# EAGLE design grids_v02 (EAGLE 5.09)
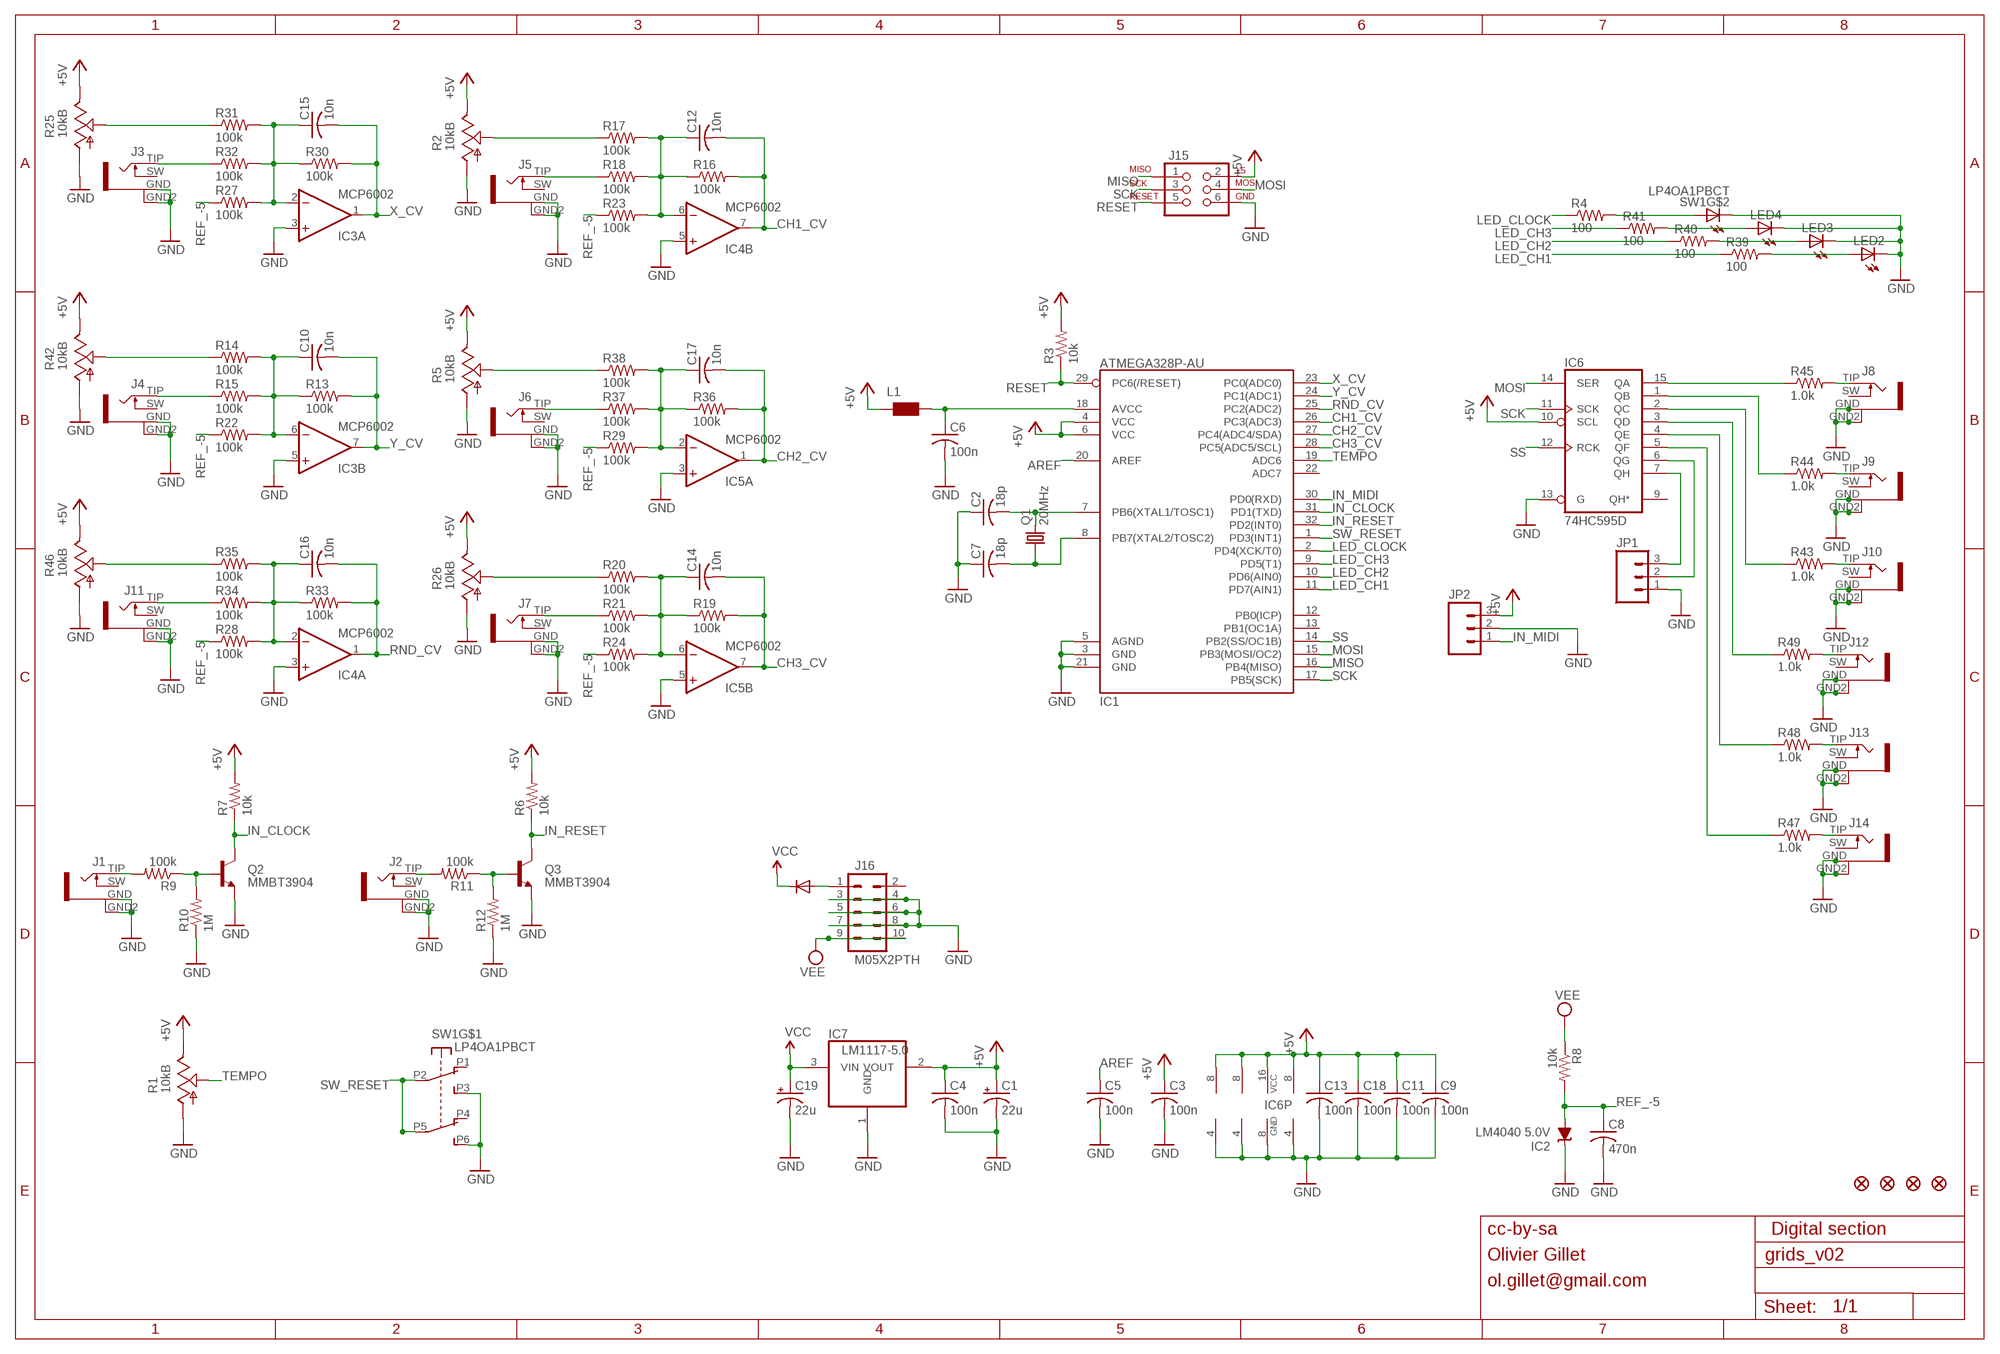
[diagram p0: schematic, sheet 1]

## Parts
C1  22u  CPOL-USC  [PANASONIC_C]
C2  18p  C-USC0603  [C0603]
C3  100n  C-USC0603  [C0603]
C4  100n  C-USC0603  [C0603]
C5  100n  C-USC0603  [C0603]
C6  100n  C-USC0603  [C0603]
C7  18p  C-USC0603  [C0603]
C8  470n  C-USC0603  [C0603]
C9  100n  C-USC0603  [C0603]
C10  10n  C-USC0603  [C0603]
C11  100n  C-USC0603  [C0603]
C12  10n  C-USC0603  [C0603]
C13  100n  C-USC0603  [C0603]
C14  10n  C-USC0603  [C0603]
C15  10n  C-USC0603  [C0603]
C16  10n  C-USC0603  [C0603]
C17  10n  C-USC0603  [C0603]
C18  100n  C-USC0603  [C0603]
C19  22u  CPOL-USC  [PANASONIC_C]
D1  1N5819HW  DIODE-SOD123  [SOD123]
F1  FIDUCIAL1X2  [FIDUCIAL-1X2]
F2  FIDUCIAL1X2  [FIDUCIAL-1X2]
F3  FIDUCIAL1X2  [FIDUCIAL-1X2]
F4  FIDUCIAL1X2  [FIDUCIAL-1X2]
IC1  ATMEGA328P-AU  ATMEGA168  [TQFP32-08]
IC2  LM4040 5.0V  LM4041C12DBZ  [DBZ_R-PDSO-G3]
IC3  MCP6002  TL072D  [SO08]
IC4  MCP6002  TL072D  [SO08]
IC5  MCP6002  TL072D  [SO08]
IC6  74HC595D  [SO16]
IC7  LM1117-5.0  REG1117  [SOT223]
J1  PJ301WQP  [WQP_PJ_301BM]
J2  PJ301WQP  [WQP_PJ_301BM]
J3  PJ301WQP  [WQP_PJ_301BM]
J4  PJ301WQP  [WQP_PJ_301BM]
J5  PJ301WQP  [WQP_PJ_301BM]
J6  PJ301WQP  [WQP_PJ_301BM]
J7  PJ301WQP  [WQP_PJ_301BM]
J8  PJ301WQP  [WQP_PJ_301BM]
J9  PJ301WQP  [WQP_PJ_301BM]
J10  PJ301WQP  [WQP_PJ_301BM]
J11  PJ301WQP  [WQP_PJ_301BM]
J12  PJ301WQP  [WQP_PJ_301BM]
J13  PJ301WQP  [WQP_PJ_301BM]
J14  PJ301WQP  [WQP_PJ_301BM]
J15  AVR_SPI_PRG_6PTH  [2X3]
J16  M05X2PTH  [AVR_ICSP]
JP1  M03PTH  [1X03]
JP2  M03PTH  [1X03]
L1  WE-CBF_0603  [0603]
LED2  LED3MM  [LED3MM]
LED3  LED3MM  [LED3MM]
LED4  LED3MM  [LED3MM]
Q1  20MHz  CRYSTALHC49UP  [HC49UP]
Q2  MMBT3904  MMBT3904LT1-NPN-SOT23-BEC  [SOT23-BEC]
Q3  MMBT3904  MMBT3904LT1-NPN-SOT23-BEC  [SOT23-BEC]
R1  10kB  POT_USVERTICAL_PS  [ALPS_POT_VERTICAL_PS]
R2  10kB  POT_USVERTICAL_PS  [ALPS_POT_VERTICAL_PS]
R3  10k  R-US_R0603  [R0603]
R4  100  R-US_R0603  [R0603]
R5  10kB  POT_USVERTICAL_PS  [ALPS_POT_VERTICAL_PS]
R6  10k  R-US_R0603  [R0603]
R7  10k  R-US_R0603  [R0603]
R8  10k  R-US_R0603  [R0603]
R9  100k  R-US_R0603  [R0603]
R10  1M  R-US_R0603  [R0603]
R11  100k  R-US_R0603  [R0603]
R12  1M  R-US_R0603  [R0603]
R13  100k  R-US_R0603  [R0603]
R14  100k  R-US_R0603  [R0603]
R15  100k  R-US_R0603  [R0603]
R16  100k  R-US_R0603  [R0603]
R17  100k  R-US_R0603  [R0603]
R18  100k  R-US_R0603  [R0603]
R19  100k  R-US_R0603  [R0603]
R20  100k  R-US_R0603  [R0603]
R21  100k  R-US_R0603  [R0603]
R22  100k  R-US_R0603  [R0603]
R23  100k  R-US_R0603  [R0603]
R24  100k  R-US_R0603  [R0603]
R25  10kB  POT_USVERTICAL_PS  [ALPS_POT_VERTICAL_PS]
R26  10kB  POT_USVERTICAL_PS  [ALPS_POT_VERTICAL_PS]
R27  100k  R-US_R0603  [R0603]
R28  100k  R-US_R0603  [R0603]
R29  100k  R-US_R0603  [R0603]
R30  100k  R-US_R0603  [R0603]
R31  100k  R-US_R0603  [R0603]
R32  100k  R-US_R0603  [R0603]
R33  100k  R-US_R0603  [R0603]
R34  100k  R-US_R0603  [R0603]
R35  100k  R-US_R0603  [R0603]
R36  100k  R-US_R0603  [R0603]
R37  100k  R-US_R0603  [R0603]
R38  100k  R-US_R0603  [R0603]
R39  100  R-US_R0603  [R0603]
R40  100  R-US_R0603  [R0603]
R41  100  R-US_R0603  [R0603]
R42  10kB  POT_USVERTICAL_PS4  [ALPS_POT_VERTICAL_PS4]
R43  1.0k  R-US_R0603  [R0603]
R44  1.0k  R-US_R0603  [R0603]
R45  1.0k  R-US_R0603  [R0603]
R46  10kB  POT_USVERTICAL_PS  [ALPS_POT_VERTICAL_PS]
R47  1.0k  R-US_R0603  [R0603]
R48  1.0k  R-US_R0603  [R0603]
R49  1.0k  R-US_R0603  [R0603]
SW1  LP4OA1PBCT  [LP4OA1PBCT]

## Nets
+5V: C1.+ C3.1 C4.1 C9.1 C11.1 C13.1 C18.1 IC1.4(VCC) IC1.6(VCC) IC3.8(P:V+) IC4.8(P:V+) IC5.8(P:V+) IC6.10(SCL) IC6.16(VCC) IC7.2(VOUT) J15.2 JP2.3 L1.1 R1.P$1(E) R2.P$1(E) R3.2 R5.P$1(E) R6.2 R7.2 R25.P$1(E) R26.P$1(E) R42.P$1(E) R46.P$1(E)
AREF: C5.1 IC1.20(AREF)
CH1_CV: C12.2 IC1.26(PC3(ADC3)) IC4.7(B:OUT) R16.2
CH2_CV: C17.2 IC1.27(PC4(ADC4/SDA)) IC5.1(A:OUT) R36.2
CH3_CV: C14.2 IC1.28(PC5(ADC5/SCL)) IC5.7(B:OUT) R19.2
CLOCK_OUT: IC6.6(QG) JP1.2
GATE1_IN: J1.TIP R9.2
GATE1_LED: R4.2 SW1.L1
GATE2_IN: J2.TIP R11.2
GATE2_LED: LED4.A R41.2
GATE3_LED: LED3.A R40.2
GATE4_LED: LED2.A R39.2
GND: C1.- C2.1 C3.2 C4.2 C5.2 C6.2 C7.1 C8.2 C9.2 C11.2 C13.2 C18.2 C19.- IC1.3(GND) IC1.5(AGND) IC1.21(GND) IC2.1(C) IC3.3(A:+IN) IC3.4(P:V-) IC3.5(B:+IN) IC4.3(A:+IN) IC4.4(P:V-) IC4.5(B:+IN) IC5.3(A:+IN) IC5.4(P:V-) IC5.5(B:+IN) IC6.8(GND) IC6.13(G) IC7.1(GND) J1.GND J1.GND2 J2.GND J2.GND2 J3.GND J3.GND2 J4.GND J4.GND2 J5.GND J5.GND2 J6.GND J6.GND2 J7.GND J7.GND2 J8.GND J8.GND2 J9.GND J9.GND2 J10.GND J10.GND2 J11.GND J11.GND2 J12.GND J12.GND2 J13.GND J13.GND2 J14.GND J14.GND2 J15.6 J16.3 J16.4 J16.5 J16.6 J16.7 J16.8 JP1.1 JP2.2 LED2.K(C) LED3.K(C) LED4.K(C) Q2.E Q3.E R1.P$3(A) R2.P$3(A) R5.P$3(A) R10.1 R12.1 R25.P$3(A) R26.P$3(A) R42.P$3(A) R46.P$3(A) SW1.L2 SW1.P3(A3) SW1.P6(B3)
IN_CLOCK: IC1.31(PD1(TXD)) Q2.C R7.1
IN_MIDI: IC1.30(PD0(RXD)) JP2.1
IN_RESET: IC1.32(PD2(INT0)) Q3.C R6.1
LED_CH1: IC1.11(PD7(AIN1)) R39.1
LED_CH2: IC1.10(PD6(AIN0)) R40.1
LED_CH3: IC1.9(PD5(T1)) R41.1
LED_CLOCK: IC1.2(PD4(XCK/T0)) R4.1
MISO: IC1.16(PB4(MISO)) J15.1
MOSI: IC1.15(PB3(MOSI/OC2)) IC6.14(SER) J15.4
N$1: Q2.B R9.1 R10.2
N$2: Q3.B R11.1 R12.2
N$3: D1.A J16.1
N$4: J14.TIP R47.2
N$5: J13.TIP R48.2
N$6: J12.TIP R49.2
N$9: R25.P$2(S) R31.1
N$10: J3.TIP R32.1
N$12: C10.1 IC3.6(B:-IN) R13.1 R14.2 R15.2 R22.2
N$13: R14.1 R42.P$2(S)
N$14: J4.TIP R15.1
N$15: C16.1 IC4.2(A:-IN) R28.2 R33.1 R34.2 R35.2
N$16: R35.1 R46.P$2(S)
N$17: J11.TIP R34.1
N$18: C12.1 IC4.6(B:-IN) R16.1 R17.2 R18.2 R23.2
N$19: R2.P$2(S) R17.1
N$20: J5.TIP R18.1
N$21: C17.1 IC5.2(A:-IN) R29.2 R36.1 R37.2 R38.2
N$22: R5.P$2(S) R38.1
N$23: J6.TIP R37.1
N$24: C14.1 IC5.6(B:-IN) R19.1 R20.2 R21.2 R24.2
N$25: R20.1 R26.P$2(S)
N$26: J7.TIP R21.1
N$27: IC6.15(QA) R45.1
N$28: IC6.1(QB) R44.1
N$29: C15.1 IC3.2(A:-IN) R27.2 R30.1 R31.2 R32.2
N$30: IC6.2(QC) R43.1
N$31: IC6.3(QD) R49.1
N$32: IC6.4(QE) R48.1
N$33: IC6.5(QF) R47.1
N$34: J8.TIP R45.2
N$35: J9.TIP R44.2
N$36: J10.TIP R43.2
N$39: C6.1 IC1.18(AVCC) L1.2
N$82: C7.2 IC1.8(PB7(XTAL2/TOSC2)) Q1.1
N$83: C2.2 IC1.7(PB6(XTAL1/TOSC1)) Q1.2
RANDOM_GATE: IC6.7(QH) JP1.3
REF_-5: C8.1 IC2.2(A) R8.2 R22.1 R23.1 R24.1 R27.1 R28.1 R29.1
RESET: IC1.29(PC6(/RESET)) J15.5 R3.1
RND_CV: C16.2 IC1.25(PC2(ADC2)) IC4.1(A:OUT) R33.2
SCK: IC1.17(PB5(SCK)) IC6.11(SCK) J15.3
SS: IC1.14(PB2(SS/OC1B)) IC6.12(RCK)
SW_RESET: IC1.1(PD3(INT1)) SW1.P2(A2) SW1.P5(B2)
TEMPO: IC1.19(ADC6) R1.P$2(S)
VCC: C19.+ D1.C IC7.3(VIN)
VEE: J16.9 J16.10 R8.1
X_CV: C15.2 IC1.23(PC0(ADC0)) IC3.1(A:OUT) R30.2
Y_CV: C10.2 IC1.24(PC1(ADC1)) IC3.7(B:OUT) R13.2
Unconnected: IC1.12(PB0(ICP)) IC1.13(PB1(OC1A)) IC1.22(ADC7) IC6.9(QH*) J1.SW J2.SW J3.SW J4.SW J5.SW J6.SW J7.SW J8.SW J9.SW J10.SW J11.SW J12.SW J13.SW J14.SW J16.2 SW1.P1(A1) SW1.P4(B1)

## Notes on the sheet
- cc-by-sa | Digital section
- Olivier Gillet
- ol.gillet@gmail.com

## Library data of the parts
C1 C19 = rcl:CPOL-US: POLARIZED CAPACITOR, American symbol
C2-C18 = rcl:C-US: CAPACITOR, American symbol
D1 = diode:DIODE-: DIODE
F1-F4 = SparkFun:FIDUCIAL: Fiducial Alignment Points
IC1 = SparkFun:ATMEGA168
IC2 = texas:LM4041: PRECISION MICROPOWER SHUNT VOLTAGE REFERENCE
IC3-IC5 = og-linear:TL072: OP AMP
IC6 = 74xx-eu:74*595: 8-bit SHIFT REGISTER, output latch
IC7 = og-vreg:REG1117: 800mA and 1A Low Dropout (LDO) Positive Regulator 1.8V, 2.5V, 2.85V, 3.3V, 5V, and Adj
J1-J14 = og-pj301:PJ301
J15 = SparkFun:AVR_SPI_PRG_6: AVR ISP 6 Pin This is the reduced ISP connector for AVR programming. Common on Arduino. This footprint will take up less PCB space and can be used with a 10-pin to 6-pin adapter such as SKU: BOB-08508
J16 = og-header:M05X2: Header 5x2 Standard 10-pin dual row 0.1" header. Commonly used with AVR-ISP. Use with Spark Fun Electronics SKU: PRT-00778
JP1 JP2 = SparkFun:M03: Header 3 Standard 3-pin 0.1" header. Use with straight break away headers (SKU : PRT-00116), right angle break away headers (PRT-00553), swiss pins (PRT-00743), machine pins (PRT-00117), and female headers (PRT-00115). Molex polarized connector foot print use with SKU : PRT-08232 with associated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
L1 = wuerth-elektronik:WE-CBF: SMD EMI Suppression Ferrite Beads
LED2-LED4 = led:LED: LED
Q1 = crystal:CRYSTAL: CRYSTAL
Q2 Q3 = transistor:*-NPN-: NPN Transistror BF959 corrected 2008.03.06
R1 R2 R5 R25 R26 R42 R46 = pot-alps:POT_US
R3 R4 R6 R7 R9-R24 R27-R41 R43-R45 R47-R49 = rcl:R-US_: RESISTOR, American symbol
R8 = resistor:R-US_: RESISTOR, American symbol
SW1 = og-switch:LP4OA1PBCT

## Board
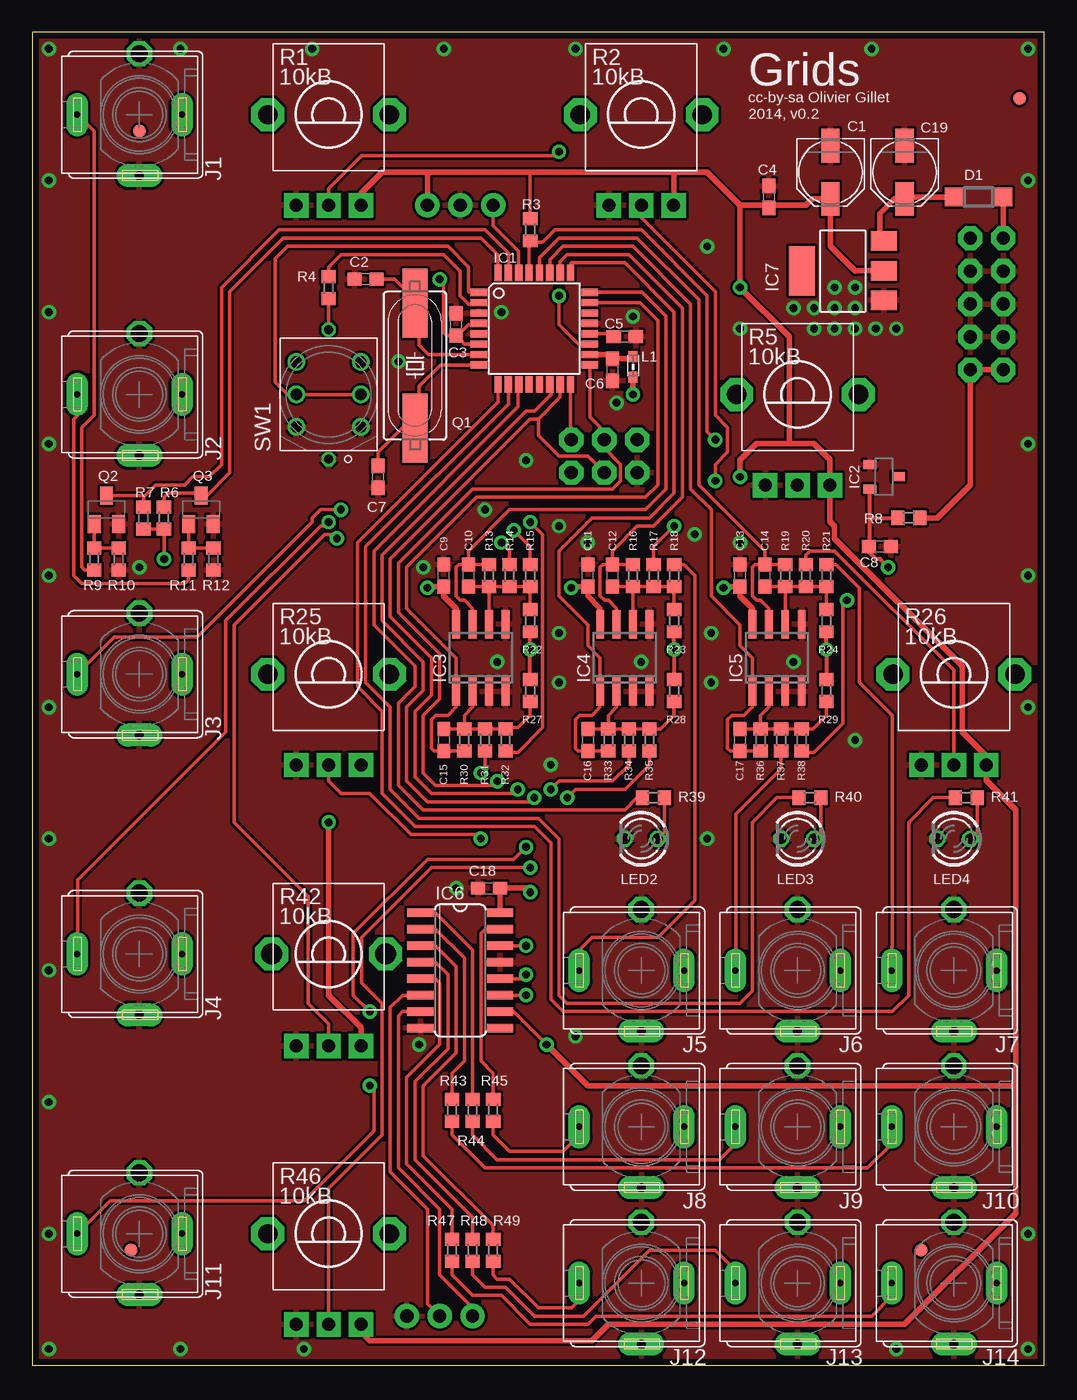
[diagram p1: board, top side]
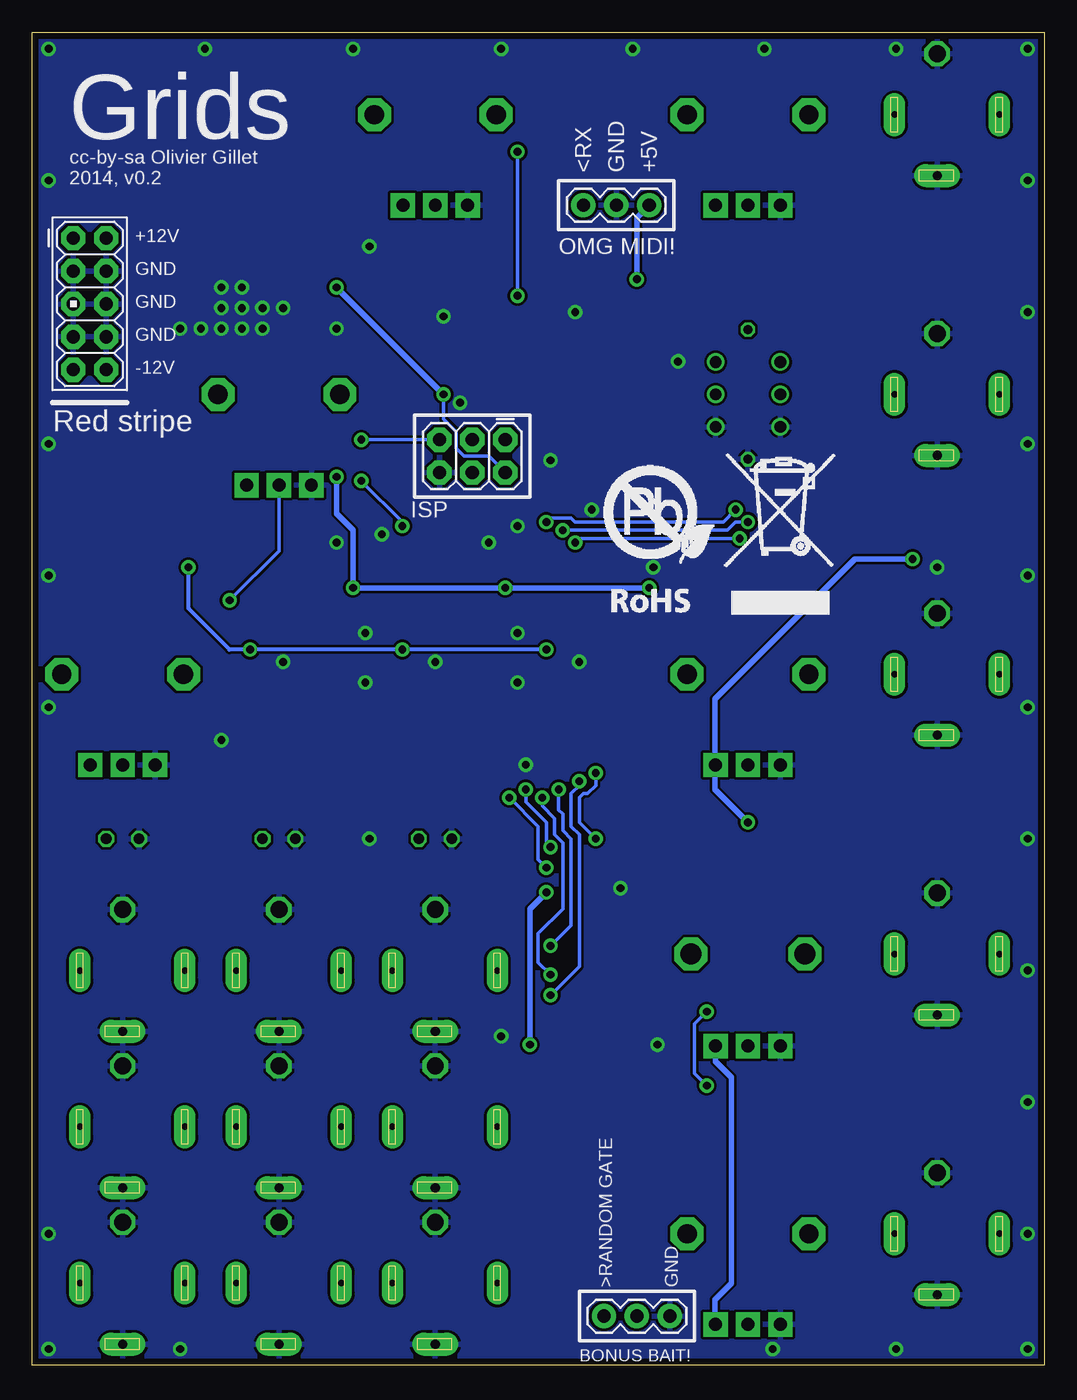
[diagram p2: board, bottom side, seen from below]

Size 78.08 x 102.87 mm. Coordinates in mm from the lower left corner, seen from the top.
Outline: 0,0 78.08,0 78.08,102.87 0,102.87 0,0
Copper layers (1*16): Top 0.035mm / dielectric 1.5mm / Bottom 0.035mm
Design rules "PCBCart-Standard *": minimum track width 8mil, minimum drill 0.4mm, track to track 8mil, track to pad 8mil, pad to pad 8mil, via to via 8mil, smd to smd 8mil, copper to edge 20mil, drill to drill 8mil, minimum pad ring 8mil, minimum via ring 10mil, stop-mask expansion 3mil, vias tented up to drill 25mil, thermal gap 8mil

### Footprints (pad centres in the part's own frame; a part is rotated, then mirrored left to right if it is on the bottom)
PANASONIC_C = smd 2.6 x 1.4: + 2.05,0; - -2.05,0
C0603 = smd 1.1 x 1: 1 -0.85,0; 2 0.85,0
SOD123 = smd 1.4 x 1.4: A 1.9,0; C -1.9,0
FIDUCIAL-1X2 = smd 1 x 1: 1 0,0
TQFP32-08 = smd 1.27 x 0.559: 1 -4.293,2.8; 2 -4.293,2; 3 -4.293,1.2; 4 -4.293,0.4; 5 -4.293,-0.4; 6 -4.293,-1.2; 7 -4.293,-2; 8 -4.293,-2.8; 17 4.293,-2.8; 18 4.293,-2; 19 4.293,-1.2; 20 4.293,-0.4; 21 4.293,0.4; 22 4.293,1.2; 23 4.293,2; 24 4.293,2.8 | smd 0.559 x 1.27: 9 -2.8,-4.293; 10 -2,-4.293; 11 -1.2,-4.293; 12 -0.4,-4.293; 13 0.4,-4.293; 14 1.2,-4.293; 15 2,-4.293; 16 2.8,-4.293; 25 2.8,4.293; 26 2,4.293; 27 1.2,4.293; 28 0.4,4.293; 29 -0.4,4.293; 30 -1.2,4.293; 31 -2,4.293; 32 -2.8,4.293
DBZ_R-PDSO-G3 = smd 0.7 x 1: 1 -0.95,-1.1; 2 0.95,-1.1; 3 0,1.1
SO08 = smd 0.6 x 2.2: 1 -1.905,-2.6; 2 -0.635,-2.6; 3 0.635,-2.6; 4 1.905,-2.6; 5 1.905,2.6; 6 0.635,2.6; 7 -0.635,2.6; 8 -1.905,2.6
SO16 = smd 0.66 x 2.032: 1 -4.445,-3.073; 2 -3.175,-3.073; 3 -1.905,-3.073; 4 -0.635,-3.073; 5 0.635,-3.073; 6 1.905,-3.073; 7 3.175,-3.073; 8 4.445,-3.073; 9 4.445,3.073; 10 3.175,3.073; 11 1.905,3.073; 12 0.635,3.073; 13 -0.635,3.073; 14 -1.905,3.073; 15 -3.175,3.073; 16 -4.445,3.073
SOT223 = smd 1.499 x 2.007: 1 -2.261,-3.15; 2 0.025,-3.15; 3 2.311,-3.15 | smd 3.81 x 2.007: 4 0,3.15
WQP_PJ_301BM = drill 0.7 pad 1.778 long: GND -4.7,0 | drill 1.3 octagon: GND2 4.7,0 | drill 0.5 pad 1.676 long: SW 0,-3.3; TIP 0,4.8
2X3 = drill 1.016 pad 1.88 octagon: 1 0,0; 2 0,2.54; 3 2.54,0; 4 2.54,2.54; 5 5.08,0; 6 5.08,2.54
AVR_ICSP = drill 1.016 pad 1.88 octagon: 1 -1.27,5.08; 2 1.27,5.08; 3 -1.27,2.54; 4 1.27,2.54; 5 -1.27,0; 6 1.27,0; 7 -1.27,-2.54; 8 1.27,-2.54; 9 -1.27,-5.08; 10 1.27,-5.08
1X03 = drill 1.016 pad 1.88 round: 1 0,0; 2 2.54,0; 3 5.08,0
0603 = smd 0.85 x 0.7: 1 -0.9,0; 2 0.7,0
LED3MM = drill 0.813 octagon: A -1.27,0; K 1.27,0
HC49UP = smd 5.334 x 1.93: 1 -4.826,0; 2 4.826,0
SOT23-BEC = smd 1 x 1.4: B -0.95,-1.1; C 0,1.1; E 0.95,-1.1
ALPS_POT_VERTICAL_PS = drill 1 pad 1.88 square: P$1 -2.5,7; P$2 0,7; P$3 2.5,7 | drill 1.5 pad 2.54 octagon: P$4 -4.7,0; P$5 4.7,0
R0603 = smd 1 x 1.1: 1 -0.85,0; 2 0.85,0
ALPS_POT_VERTICAL_PS4 = drill 1 pad 1.88 square: P$1 -2.5,7.1; P$2 0,7.1; P$3 2.5,7.1 | drill 1.6 pad 2.54 octagon: P$4 -4.4,0; P$5 4.4,0
LP4OA1PBCT = drill 0.7 octagon: L1 5,0; L2 -5,0 | drill 0.9 round: P1 2.5,2.5; P2 0,2.5; P3 -2.5,2.5; P4 2.5,-2.5; P5 0,-2.5; P6 -2.5,-2.5

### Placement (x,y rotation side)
C1  61.59,92.08 270 top
C2  25.72,83.82 0 top
C3  32.7,80.33 90 top
C4  56.83,90.17 90 top
C5  45.72,79.38 0 top
C6  44.77,76.83 270 top
C7  26.67,68.58 90 top
C8  65.41,63.18 0 top
C9  31.75,60.96 90 top
C10  33.66,60.96 90 top
C11  42.86,60.96 90 top
C12  44.77,60.96 90 top
C13  54.61,60.96 90 top
C14  56.52,60.96 90 top
C15  31.75,48.26 270 top
C16  42.86,48.26 270 top
C17  54.61,48.26 270 top
C18  35.24,36.83 180 top
C19  67.31,92.08 270 top
D1  73.03,90.17 0 top
F1  76.2,97.79 90 top
F2  8.26,95.25 90 top
F3  7.62,8.89 90 top
F4  68.58,8.89 90 top
IC1  38.73,80.01 0 top
IC2  65.72,68.58 270 top
IC3  34.61,54.61 0 top
IC4  45.72,54.61 0 top
IC5  57.47,54.61 0 top
IC6  33.02,30.48 270 top
IC7  62.55,84.45 90 top
J1  8.26,96.52 90 top
J2  8.26,74.93 90 top
J3  8.26,53.34 90 top
J4  8.26,31.75 90 top
J5  46.99,30.48 90 top
J6  59.05,30.48 90 top
J7  71.12,30.48 90 top
J8  46.99,18.41 90 top
J9  59.05,18.41 90 top
J10  71.12,18.41 90 top
J11  8.26,10.16 90 top
J12  46.99,6.35 90 top
J13  59.05,6.35 90 top
J14  71.12,6.35 90 top
J15  41.59,71.44 180 bottom
J16  73.66,81.92 0 bottom
JP1  28.89,3.81 180 bottom
JP2  35.56,89.53 0 bottom
L1  46.35,77.15 90 top
LED2  46.99,40.64 180 top
LED3  59.05,40.64 180 top
LED4  71.12,40.64 180 top
Q1  29.53,77.15 90 top
Q2  5.71,66.04 0 top
Q3  13.02,66.04 0 top
R1  22.86,96.52 180 top
R2  46.99,96.52 180 top
R3  38.42,87.63 90 top
R4  22.86,83.19 270 top
R5  59.05,74.93 180 top
R6  10.16,65.41 270 top
R7  8.57,65.41 270 top
R8  67.63,65.41 180 top
R9  4.76,62.23 270 top
R10  6.67,62.23 90 top
R11  12.06,62.23 270 top
R12  13.97,62.23 90 top
R13  35.24,60.96 90 top
R14  36.83,60.96 270 top
R15  38.42,60.96 270 top
R16  46.35,60.96 90 top
R17  47.94,60.96 270 top
R18  49.53,60.96 270 top
R19  58.1,60.96 90 top
R20  59.69,60.96 270 top
R21  61.28,60.96 270 top
R22  38.42,57.47 90 top
R23  49.53,57.47 90 top
R24  61.28,57.47 90 top
R25  22.86,53.34 180 top
R26  71.12,53.34 180 top
R27  38.42,52.07 270 top
R28  49.53,52.07 270 top
R29  61.28,52.07 270 top
R30  33.34,48.26 270 top
R31  34.92,48.26 90 top
R32  36.51,48.26 90 top
R33  44.45,48.26 270 top
R34  46.04,48.26 90 top
R35  47.62,48.26 90 top
R36  56.2,48.26 270 top
R37  57.78,48.26 90 top
R38  59.37,48.26 90 top
R39  47.94,43.81 0 top
R40  60.01,43.81 0 top
R41  72.07,43.81 0 top
R42  22.86,31.75 180 top
R43  32.38,19.68 270 top
R44  33.97,19.68 270 top
R45  35.56,19.68 270 top
R46  22.86,10.16 180 top
R47  32.38,8.89 270 top
R48  33.97,8.89 270 top
R49  35.56,8.89 270 top
SW1  22.86,74.93 90 top
U$1  [EURORACK_TEMPLATE]  not placed on the board
U$2  [ROHS_BIG]  35.24,57.15 0 bottom

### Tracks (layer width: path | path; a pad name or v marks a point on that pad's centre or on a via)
+5V  (via drill 0.6)
  Top 0.254: v39.69,24.77 37.15,27.3 IC6.10 | 38.42,92.08 R3.2 | 34.51,78.74 IC1.6 33.37,78.81 33.07,79.11 | v10.16,62.23 R6.2 R7.2 | v31.43,83.82 31.75,83.5 31.75,79.69 31.96,79.48 C3.1 33.07,79.11 | IC1.4 34.36,80.33 33.66,80.33 33.07,79.74 33.07,79.11
  Top 0.406: 30.48,92.08 26.99,92.08 25.36,90.45 R1.P$1 | 30.48,92.08 38.42,92.08 49.53,92.08 | v39.69,24.77 42.86,21.59 75.88,21.59 | IC3.8 32.66,57.25 32.7,57.3 32.7,58.42 31.75,59.37 C9.1 30.58,60.11 v30.48,60.01 | IC4.8 43.77,57.25 43.81,57.3 43.81,58.42 42.86,59.37 C11.1 41.7,60.11 v41.59,60.01 | v46.35,74.93 L1.1 | IC5.8 55.56,58.42 54.61,59.37 C13.1 | C13.1 54.51,60.01 | v38.42,36.51 38.1,36.83 C18.1 IC6.16 | v22.86,41.91 22.86,28.57 25.36,26.07 R42.P$1 | 75.88,21.59 75.88,42.86 73.62,45.12 R26.P$1 73.66,46.38 73.66,46.99 71.75,48.9 71.75,53.98 61.91,63.82 61.91,64.77 61.55,65.13 R5.P$1 61.55,69.89 60.33,71.12 58.42,71.12 | R46.P$1 25.36,2.58 26.04,1.91 43.18,1.91 44.45,3.17 67.31,3.17 75.88,11.75 75.88,21.59 | v53.34,60.01 53.44,60.11 C13.1 | v54.61,68.58 54.61,69.85 55.88,71.12 58.42,71.12 | 30.48,92.08 JP2.3 | R2.P$1 49.53,89.56 49.53,92.08 | 58.42,71.12 58.42,79.38 v54.61,83.19 54.61,89.53 | IC7.2 63.5,84.48 63.5,84.45 61.59,86.36 C1.+ 60.18,90.03 59.69,89.53 57.05,89.53 C4.1 56.62,89.53 54.61,89.53 | 49.53,92.08 52.07,92.08 54.61,89.53
  Bottom 0.254: J15.2 42.86,70.17 44.77,70.17 45.4,70.8 45.4,72.07 46.35,73.03 v46.35,74.93
  Bottom 0.406: v39.69,24.77 39.69,35.24 v38.42,36.51 | v30.48,60.01 v41.59,60.01 v53.34,60.01 53.34,64.45 54.61,65.72 v54.61,68.58 | v54.61,83.19 v46.35,74.93 | JP2.3 31.43,88.58 v31.43,83.82 | v22.86,41.91 25.4,44.45 25.4,46.3 R25.P$1 25.36,46.64 25.4,46.68 25.4,51.44 14.61,62.23 v10.16,62.23 | R46.P$1 25.4,3.2 25.4,5.08 24.13,6.35 24.13,22.23 25.36,23.45 R42.P$1
AREF
  Top 0.254: C5.1 44.63,79.61 IC1.20
CH1_CV
  Top 0.254: IC4.7 45.09,58.42 44.45,59.05 44.13,59.05 43.81,59.37 43.81,61.59 44.03,61.81 C12.2 | C12.2 R16.2 | C12.2 44.77,62.87 46.67,64.77 47.94,64.77 50.16,66.99 50.16,81.6 46.04,85.72 41.27,85.72 40.73,85.19 IC1.26
CH2_CV
  Top 0.254: IC1.27 39.94,85.34 40.96,86.36 46.35,86.36 50.8,81.92 50.8,67.63 52.39,66.04 52.39,59.37 54.61,57.15 54.61,55.56 55.56,54.61 IC5.1 55.56,50.8 54.93,50.16 53.98,50.16 53.66,49.85 53.66,47.62 53.87,47.41 C17.2 R36.2
CH3_CV
  Top 0.254: C14.2 56.52,62.87 51.44,67.94 51.44,82.23 46.67,87 40.64,87 39.13,85.49 IC1.28 | IC5.7 56.83,58.42 56.2,59.05 55.88,59.05 55.56,59.37 55.56,61.59 55.78,61.81 C14.2 | C14.2 R19.2
CLOCK_OUT
  Top 0.254: IC6.6 28.57,28.57 27.62,27.62 27.62,14.92 30.48,12.06 30.48,4.76 JP1.2
GATE1_IN
  Top 0.254: R9.2 4.03,61.38 3.81,61.59 3.81,72.39 4.76,73.34 4.76,95.25 3.49,96.52 J1.TIP
GATE1_LED
  Top 0.254: SW1.L1 R4.2
GATE2_IN
  Top 0.254: J2.TIP 3.49,74.89 3.49,73.34 3.17,73.03 3.17,60.96 3.81,60.33 11.75,60.33 12.06,60.64 R11.2
GATE2_LED
  Top 0.254: LED4.A 72.92,41.17 R41.2
GATE3_LED
  Top 0.254: LED3.A 60.86,41.17 R40.2
GATE4_LED
  Top 0.254: LED2.A 48.79,41.17 R39.2
GND  (via drill 0.6)
  other vias: 8.26,61.59 46.35,80.96 46.99,54.29 58.74,54.29 42.86,63.5 54.61,63.5 35.88,54.29 30.16,61.59 45.09,74.3 36.2,81.28 40.01,46.35 40.64,52.7 32.7,36.83 29.84,24.77 28.26,77.47 52.07,86.36 54.61,80.01 38.1,69.85 52.39,52.7 40.64,56.52 52.39,56.52 41.91,25.4 34.92,66.04 40.64,64.77 51.12,64.14 1.27,20.32 11.43,1.27 1.27,30.48 1.27,81.28 1.27,91.44 20.95,1.27 1.27,101.6 1.27,1.27 63.5,48.26 76.83,101.6 76.83,91.44 76.83,71.12 76.83,60.96 76.83,50.8 76.83,1.27 66.67,1.27 76.83,10.16 52.07,40.64 1.27,60.96 1.27,50.8 1.27,71.12 1.27,40.64 1.27,10.16 11.43,101.6 21.59,101.6 31.75,101.6 41.91,101.6 53.34,101.6 64.77,101.6 63.5,83.19 63.5,81.6 61.91,83.19 61.91,81.6 63.5,80.01 65.09,80.01 61.91,80.01 66.67,80.01 60.33,80.01 60.33,81.6 58.74,81.6
  pour Bottom: 0,102.87 0,0 78.11,0 78.11,102.87
  pour Top: 0,102.87 0,0 78.11,0 78.11,102.87
IN_CLOCK
  Top 0.254: 8.57,66.99 9.53,67.94 11.75,67.94 12.38,68.58 13.65,68.58 14.61,69.53 14.61,83.19 19.05,87.63 34.92,87.63 36.73,85.82 IC1.31 | 8.57,66.99 R7.1 | 8.57,66.99 8.43,67.14 Q2.C
IN_MIDI
  Top 0.254: JP2.1 35.56,87.95 37.53,85.97 IC1.30
IN_RESET
  Top 0.254: IC1.32 35.94,85.67 34.61,87 19.37,87 15.24,82.87 15.24,68.9 13.48,67.14 Q3.C 12.85,67.31 10.48,67.31 10.16,66.99 R6.1
LED_CH1
  Top 0.254: IC1.11 37.47,75.65 37.47,73.98 26.35,62.87 26.35,57.15 29.53,53.98 29.53,52.39 28.26,51.12 28.26,44.77 30.16,42.86 45.72,42.86 46.67,43.81 R39.1
LED_CH2
  Top 0.254: 36.83,75.62 IC1.10 36.73,74.2 25.72,63.18 25.72,52.7 27.62,50.8 27.62,44.45 29.84,42.23 39.05,42.23 40.64,40.64 40.64,28.57 41.27,27.94 54.61,27.94 55.56,28.89 55.56,41.91 57.47,43.81 R40.1
LED_CH3
  Top 0.254: 35.88,75.66 IC1.9 35.94,74.35 25.08,63.5 25.08,52.39 26.99,50.48 26.99,44.13 29.53,41.59 38.73,41.59 40.01,40.32 40.01,28.26 40.96,27.3 66.36,27.3 67.63,28.57 67.63,41.91 69.53,43.81 R41.1
LED_CLOCK
  Top 0.254: IC1.2 34.35,81.92 33.66,81.92 33.02,82.55 33.02,84.45 31.75,85.72 23.81,85.72 22.86,84.77 R4.1
MISO
  Top 0.254: J15.1 41.59,72.39 41.53,72.45 IC1.16
MOSI  (via drill 0.6)
  Top 0.254: J15.4 42.86,70.17 40.64,70.17 39.05,71.75 39.05,73.03 | v37.47,44.45 37.15,44.13 30.8,44.13 29.53,45.4 29.53,50.48 30.8,51.75 30.8,54.61 27.62,57.78 27.62,62.23 38.42,73.03 39.05,73.03 | IC6.14 v38.1,32.38 | 39.05,73.03 40.73,74.71 IC1.15
  Bottom 0.254: v37.47,44.45 37.47,42.86 37.15,42.55 37.15,41.27 36.51,40.64 36.51,33.97 v38.1,32.38
N$1
  Top 0.254: R10.2 R9.1 Q2.B
N$2
  Top 0.254: R12.2 R11.1 Q3.B
N$3
  Top 0.406: J16.1 D1.A
N$4
  Top 0.254: J14.TIP 66.32,5.36 64.77,3.81 43.5,3.81 42.86,3.17 38.42,3.17 36.2,5.4 33.97,5.4 32.38,6.99 R47.2
N$5
  Top 0.254: J13.TIP 54.26,7.34 52.7,8.89 47.62,8.89 42.55,3.81 38.73,3.81 36.51,6.03 34.92,6.03 33.97,6.99 R48.2
N$6
  Top 0.254: J12.TIP 42.19,5.04 41.59,4.45 39.05,4.45 36.83,6.67 35.88,6.67 35.56,6.99 R49.2
N$9  (via drill 0.6)
  Top 0.254: v34.61,40.64 34.29,40.96 29.21,40.96 26.04,44.13 23.81,44.13 22.86,45.09 R25.P$2 | v34.61,45.72 34.92,46.04 R31.1
  Bottom 0.254: v34.61,40.64 35.88,41.91 35.88,43.81 35.56,44.13 35.24,44.13 34.61,44.77 v34.61,45.72
N$10  (via drill 0.6)
  Top 0.254: J3.TIP 6.31,56.2 12.7,56.2 21.59,65.09 21.59,65.41 22.23,66.04 v23.81,66.04 | R32.1 36.62,47.31 37.47,47.31 39.37,49.21 39.37,64.14 v38.42,65.09
  Bottom 0.254: v38.42,65.09 38.1,65.41 36.51,65.41 36.2,65.09 24.77,65.09 v23.81,66.04
N$12
  Top 0.254: R13.1 C10.1 | IC3.6 R13.1 | R13.1 R14.2 R15.2 R22.2
N$13  (via drill 0.6)
  Top 0.254: R42.P$2 22.86,26.35 21.27,27.94 21.27,36.2 15.56,41.91 15.56,57.15 22.54,64.14 23.18,64.14 v23.5,63.82 | v36.2,63.5 36.83,62.87 R14.1
  Bottom 0.254: v23.5,63.82 35.88,63.82 v36.2,63.5
N$14  (via drill 0.6)
  Top 0.254: J4.TIP 3.49,31.79 3.49,37.47 14.92,48.9 14.92,57.47 22.23,64.77 22.54,64.77 v22.86,65.09 | v37.15,64.45 38.42,63.18 R15.1
  Bottom 0.254: v37.15,64.45 24.45,64.45 23.81,65.09 v22.86,65.09
N$15
  Top 0.254: C16.1 R33.1 | IC4.2 45.09,50.8 44.45,50.16 R33.1 | R33.1 R34.2 R35.2 48.48,49.11 49.53,50.16 R28.2
N$16  (via drill 0.6)
  Top 0.254: R35.1 47.62,46.35 45.72,44.45 41.91,44.45 v41.27,43.81 | R46.P$2 22.86,13.65 26.99,17.78 26.99,27.94 25.4,29.53 25.4,33.02 30.8,38.42 v38.42,38.42
  Bottom 0.254: v38.42,38.42 39.05,39.05 39.05,41.59 v41.27,43.81
N$17  (via drill 0.6)
  Top 0.254: R34.1 46.04,46.35 44.77,45.09 40.64,45.09 v40.01,44.45 | J11.TIP 6,12.7 20.95,12.7 26.35,18.1 26.35,21.27 v26.04,21.59 | v38.1,40.01 37.15,39.05 30.48,39.05 24.77,33.34 24.77,28.57 v26.04,27.3
  Bottom 0.254: v38.1,40.01 38.42,40.32 38.42,41.91 40.01,43.5 v40.01,44.45 | v26.04,27.3 26.99,26.35 26.99,22.54 v26.04,21.59
N$18
  Top 0.254: R16.1 IC4.6 | C12.1 R16.1 | R16.1 R17.2 R18.2 R23.2
N$19  (via drill 0.6)
  Top 0.254: R2.P$2 46.99,88.58 52.7,82.87 52.7,73.34 53.66,72.39 53.66,70.48 52.7,69.53 v52.7,68.26 | v49.53,64.77 47.94,63.18 R17.1
  Bottom 0.254: v49.53,64.77 49.53,65.09 v52.7,68.26
N$20
  Top 0.254: J5.TIP 42.19,32.03 43.18,33.02 48.26,33.02 51.12,35.88 51.12,60.96 50.27,61.81 R18.1
N$21
  Top 0.254: IC5.2 56.83,50.8 56.2,50.16 R36.1 | C17.1 R36.1 | R36.1 56.3,49.21 56.52,49.21 56.62,49.11 R37.2 R38.2 60.22,49.11 61.28,50.16 R29.2
N$22  (via drill 0.6)
  Top 0.254: R38.1 59.48,47.31 60.33,47.31 62.55,49.53 62.55,58.74 v62.87,59.05
  Bottom 0.254: v62.87,59.05 59.05,62.87 R5.P$2
N$23
  Top 0.254: R37.1 57.78,46.04 54.29,42.55 54.29,31.75 54.26,31.71 J6.TIP
N$24
  Top 0.254: IC5.6 R19.1 | R19.1 C14.1 | R19.1 R20.2 R21.2 R24.2
N$25
  Top 0.254: R20.1 59.69,62.55 60.01,62.87 61.91,62.87 71.12,53.66 R26.P$2
N$26
  Top 0.254: J7.TIP 66.32,32.35 66.36,32.38 66.36,50.16 63.82,52.7 63.82,60.01 62.02,61.81 R21.1
N$27
  Top 0.254: R45.1 35.56,22.54 34.61,23.5 34.61,33.34 34.92,33.66 IC6.15
N$28
  Top 0.254: R44.1 33.97,32.07 31.11,34.92 IC6.1
N$29
  Top 0.254: IC3.2 33.97,50.8 33.34,50.16 R30.1 | R30.1 R31.2 R32.2 36.62,49.21 37.47,49.21 38.42,50.16 R27.2 | C15.1 R30.1
N$30
  Top 0.254: R43.1 32.38,22.54 33.34,23.5 33.34,31.43 31.11,33.66 IC6.2
N$31
  Top 0.254: IC6.3 31.11,32.38 32.7,30.8 32.7,24.13 30.16,21.59 30.16,16.19 35.56,10.79 R49.1
N$32
  Top 0.254: IC6.4 31.11,31.11 32.07,30.16 32.07,24.45 29.53,21.91 29.53,15.88 33.97,11.43 R48.1
N$33
  Top 0.254: IC6.5 31.11,29.84 31.43,29.53 31.43,24.77 28.89,22.23 28.89,15.56 32.38,12.06 R47.1
N$34
  Top 0.254: R45.2 35.56,17.78 36.83,16.51 40.96,16.51 42.19,17.74 J8.TIP
N$35
  Top 0.254: R44.2 33.97,17.78 35.88,15.88 53.02,15.88 54.26,17.11 J9.TIP
N$36
  Top 0.254: R43.2 32.38,17.78 34.92,15.24 64.45,15.24 66.32,17.11 J10.TIP
N$39
  Top 0.406: IC1.18 44.44,78.01 C6.1 46.19,77.69 L1.2
N$82
  Top 0.254: C7.2 26.67,70.48 28.51,72.33 Q1.1 29.84,72.64 29.84,75.56 31.49,77.21 IC1.8
N$83
  Top 0.254: C2.2 27.94,83.82 29.53,82.23 Q1.2 29.84,81.66 29.84,78.74 30.57,78.01 IC1.7
RANDOM_GATE
  Top 0.254: IC6.7 28.57,27.3 28.26,26.99 28.26,15.24 31.43,12.06 31.43,6.99 33.97,4.45 JP1.3
REF_-5  (via drill 0.6)
  Top 0.305: R29.1 v61.28,55.24 R24.1 | R27.1 v38.42,55.24 R22.1 | R23.1 v49.53,55.24 R28.1 | 64.62,65.41 64.62,63.25 C8.1 64.56,62.76 65.09,62.23 65.41,62.23 v66.04,61.59 | 64.62,65.41 IC2.2 | 66.61,65.58 66.44,65.41 64.62,65.41
  Top 0.406: 66.61,65.58 R8.2
  Bottom 0.305: v38.42,55.24 v49.53,55.24 v61.28,55.24 62.87,55.24 66.04,58.42 v66.04,61.59
RESET  (via drill 0.6)
  Top 0.254: R3.1 38.34,86.7 38.35,86.68 | 38.35,86.68 39.37,86.68 40.32,87.63 46.99,87.63 52.07,82.55 52.07,72.07 v52.7,71.44 | 38.35,86.68 38.34,86.66 IC1.29
  Bottom 0.254: J15.5 v52.7,71.44
RND_CV
  Top 0.254: R33.2 C16.2 42.12,47.41 41.91,47.62 41.91,49.85 42.23,50.16 43.18,50.16 43.81,50.8 IC4.1 43.81,54.61 42.86,55.56 42.86,57.15 40.64,59.37 40.64,62.87 43.18,65.41 47.62,65.41 49.53,67.31 49.53,81.28 45.72,85.09 41.59,85.09 41.53,85.03 IC1.25
SCK  (via drill 0.6)
  Top 0.254: IC1.17 43.03,73.18 44.13,72.07 J15.3 44.13,70.8 45.4,69.53 45.4,68.26 44.77,67.63 33.97,67.63 28.26,61.91 28.26,58.1 31.43,54.93 31.43,51.44 30.16,50.16 30.16,45.72 31.11,44.77 35.56,44.77 v35.88,45.09 | IC6.11 v38.1,28.57
  Bottom 0.254: v35.88,45.09 35.88,44.77 36.51,44.13 36.51,41.59 35.88,40.96 35.88,30.8 v38.1,28.57
SS  (via drill 0.6)
  Top 0.254: IC1.14 40.01,75.65 40.01,74.93 38.73,73.66 38.1,73.66 26.99,62.55 26.99,57.47 30.16,54.29 30.16,52.07 28.89,50.8 28.89,45.09 30.48,43.5 38.42,43.5 v38.73,43.81 | IC6.12 37.78,29.84 v38.1,30.16
  Bottom 0.254: v38.73,43.81 38.73,43.18 37.78,42.23 37.78,40.96 37.15,40.32 37.15,35.24 39.05,33.34 39.05,31.11 v38.1,30.16
SW_RESET
  Top 0.254: IC1.1 33.71,82.81 33.66,82.87 33.66,84.77 32.07,86.36 19.68,86.36 18.73,85.41 18.73,75.88 19.68,74.93 SW1.P2 SW1.P5
TEMPO  (via drill 0.6)
  Top 0.254: R1.P$2 22.86,90.81 25.4,93.34 40.32,93.34 v40.64,93.66 | v40.64,82.55 40.64,80.33 42.16,78.81 IC1.19
  Bottom 0.254: v40.64,93.66 v40.64,82.55
VCC
  Top 0.406: IC7.3 65.41,87.06 65.41,88.9 66.53,90.03 C19.+ 67.45,90.17 D1.C
VEE
  Top 0.406: R8.1 69.85,65.41 72.39,67.94 J16.10 J16.9
X_CV
  Top 0.254: IC1.23 46.9,82.01 48.26,80.64 48.26,67.94 47.31,66.99 34.29,66.99 28.89,61.59 28.89,58.42 32.7,54.61 IC3.1 32.7,50.8 32.07,50.16 31.11,50.16 30.8,49.85 30.8,47.62 31.01,47.41 C15.2 R30.2
Y_CV
  Top 0.254: IC1.24 47.05,82.81 48.9,80.96 48.9,67.63 47.31,66.04 36.83,66.04 33.66,62.87 C10.2 | C10.2 R13.2 | IC3.7 33.97,58.42 33.34,59.05 33.02,59.05 32.7,59.37 32.7,61.59 32.92,61.81 C10.2

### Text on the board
bPlace: Red stripe
tNames: Grids | cc-by-sa Olivier Gillet | 2014, v0.2
bNames: Grids | cc-by-sa Olivier Gillet | +5V | GND | <RX | 2014, v0.2 | +12V | OMG MIDI! | GND | GND | GND | -12V | ISP | GND | >RANDOM GATE | BONUS BAIT!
